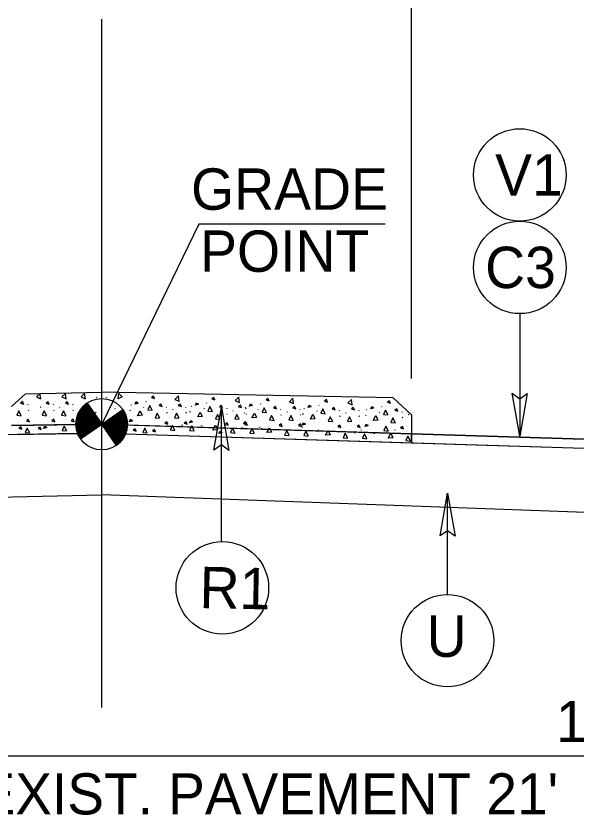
# Model space of a CAD drawing. Extents: x 2176156 to 2177167, y 76401 to 76644.
# Drawn here: x 2176819.12 to 2176834.8, y 76511.75 to 76534.15 of the extents above; entities that cross this region are included whole.
import ezdxf

# ---------------------------------------------------------------- set-up
doc = ezdxf.new("R2010")
doc.units = 0
for name, color, linetype in [('Exist Roads Change in Surface', 7, 'Continuous'), ('Exist Roads Curbs', 7, 'Continuous'), ('Exist Roads Soil', 7, 'Continuous'), ('Exist Structure Minor Culvert Topo', 7, 'Continuous'), ('Old_Level_3', 7, 'Continuous'), ('Prop North Arrow NAD83 for Plan Sheets CELL', 7, 'Continuous'), ('Sheet Plan CELL', 7, 'Continuous')]:
    doc.layers.add(name, color=color, linetype=linetype)

msp = doc.modelspace()

# ---------------------------------------------------------------- linework, layer by layer
at = {"layer": 'Exist Roads Change in Surface'}
for p, q in [((2176821.385, 76523.44), (2176821.375, 76523.464)), ((2176821.652, 76523.44), (2176821.663, 76523.464)), ((2176819.455, 76523.251), (2176819.444, 76523.235)), ((2176820.168, 76523.251), (2176820.157, 76523.235)), ((2176820.707, 76523.251), (2176820.696, 76523.235)), ((2176821.107, 76523.294), (2176821.519, 76522.702)), ((2176822.33, 76523.251), (2176822.341, 76523.235)), ((2176822.764, 76523.336), (2176822.754, 76523.32)), ((2176824.019, 76523.217), (2176824.029, 76523.201)), ((2176824.453, 76523.302), (2176824.442, 76523.286)), ((2176825.968, 76523.272), (2176825.958, 76523.256)), ((2176827.61, 76523.239), (2176827.599, 76523.223)), ((2176819.475, 76523.075), (2176819.464, 76523.099)), ((2176819.809, 76523.183), (2176819.798, 76523.167)), ((2176820.188, 76523.075), (2176820.177, 76523.099)), ((2176820.348, 76523.183), (2176820.337, 76523.167)), ((2176820.727, 76523.075), (2176820.716, 76523.099)), ((2176821.143, 76523.131), (2176821.132, 76523.155)), ((2176821.359, 76523.014), (2176821.348, 76523.038)), ((2176821.519, 76522.702), (2176822.11, 76523.114)), ((2176821.679, 76523.014), (2176821.69, 76523.038)), ((2176821.895, 76523.131), (2176821.905, 76523.155)), ((2176822.31, 76523.075), (2176822.321, 76523.099)), ((2176822.689, 76523.183), (2176822.7, 76523.167)), ((2176823.333, 76523.183), (2176823.322, 76523.167)), ((2176823.353, 76523.007), (2176823.342, 76523.031)), ((2176823.513, 76523.115), (2176823.502, 76523.099)), ((2176823.872, 76523.183), (2176823.861, 76523.167)), ((2176823.892, 76523.007), (2176823.881, 76523.031)), ((2176823.998, 76523.041), (2176824.009, 76523.065)), ((2176824.378, 76523.149), (2176824.388, 76523.133)), ((2176825.021, 76523.149), (2176825.01, 76523.133)), ((2176825.041, 76522.974), (2176825.03, 76522.998)), ((2176825.201, 76523.081), (2176825.191, 76523.065)), ((2176825.514, 76523.011), (2176825.525, 76523.035)), ((2176825.534, 76523.186), (2176825.545, 76523.17)), ((2176825.56, 76523.149), (2176825.55, 76523.133)), ((2176825.58, 76522.974), (2176825.57, 76522.998)), ((2176825.893, 76523.119), (2176825.904, 76523.103)), ((2176826.536, 76523.119), (2176826.526, 76523.103)), ((2176826.717, 76523.051), (2176826.706, 76523.035)), ((2176827.076, 76523.119), (2176827.065, 76523.103)), ((2176827.155, 76522.978), (2176827.166, 76523.002)), ((2176827.176, 76523.154), (2176827.186, 76523.138)), ((2176827.535, 76523.086), (2176827.545, 76523.07)), ((2176828.178, 76523.086), (2176828.167, 76523.07)), ((2176828.358, 76523.018), (2176828.348, 76523.002)), ((2176828.717, 76523.086), (2176828.707, 76523.07)), ((2176828.933, 76523.118), (2176828.944, 76523.102)), ((2176829.292, 76523.051), (2176829.303, 76523.035)), ((2176829.368, 76523.204), (2176829.357, 76523.188)), ((2176829.936, 76523.051), (2176829.925, 76523.035)), ((2176821.026, 76522.843), (2176821.015, 76522.827)), ((2176822.012, 76522.843), (2176822.023, 76522.827)), ((2176826.556, 76522.943), (2176826.546, 76522.967)), ((2176827.096, 76522.943), (2176827.085, 76522.967)), ((2176828.198, 76522.911), (2176828.187, 76522.935)), ((2176828.737, 76522.911), (2176828.727, 76522.935)), ((2176828.913, 76522.943), (2176828.924, 76522.967)), ((2176829.956, 76522.875), (2176829.945, 76522.899)), ((2176830.116, 76522.983), (2176830.106, 76522.967)), ((2176820.926, 76522.292), (2176821.519, 76522.702)), ((2176821.519, 76522.702), (2176820.926, 76522.292)), ((2176821.93, 76522.11), (2176821.519, 76522.702)), ((2176823.779, 76522.659), (2176823.769, 76522.683)), ((2176824.319, 76522.645), (2176824.309, 76522.669)), ((2176825.466, 76522.582), (2176825.456, 76522.606)), ((2176825.94, 76522.607), (2176825.951, 76522.631)), ((2176826.005, 76522.568), (2176825.995, 76522.592)), ((2176827.143, 76522.617), (2176827.132, 76522.601)), ((2176827.58, 76522.532), (2176827.591, 76522.556)), ((2176829.718, 76522.55), (2176829.728, 76522.534)), ((2176826.98, 76522.513), (2176826.97, 76522.537)), ((2176827.52, 76522.499), (2176827.51, 76522.523)), ((2176828.621, 76522.438), (2176828.61, 76522.462)), ((2176828.784, 76522.542), (2176828.773, 76522.526)), ((2176829.16, 76522.424), (2176829.15, 76522.449)), ((2176829.336, 76522.452), (2176829.348, 76522.476))]:
    msp.add_line(p, q, dxfattribs=at)
for points in [[(2176819.809, 76523.412), (2176819.788, 76523.564), (2176819.692, 76523.466), (2176819.806, 76523.413)], [(2176820.522, 76523.412), (2176820.501, 76523.564), (2176820.405, 76523.466), (2176820.519, 76523.413)], [(2176821.061, 76523.412), (2176821.04, 76523.564), (2176820.945, 76523.466), (2176821.059, 76523.413)], [(2176821.976, 76523.412), (2176821.997, 76523.564), (2176822.093, 76523.466), (2176821.979, 76523.413)], [(2176823.001, 76523.422), (2176822.969, 76523.489), (2176822.916, 76523.449), (2176823.001, 76523.422)], [(2176823.687, 76523.345), (2176823.665, 76523.497), (2176823.57, 76523.398), (2176823.684, 76523.345)], [(2176824.689, 76523.388), (2176824.657, 76523.455), (2176824.604, 76523.415), (2176824.689, 76523.388)], [(2176825.375, 76523.311), (2176825.354, 76523.463), (2176825.258, 76523.365), (2176825.372, 76523.312)], [(2176819.333, 76523.269), (2176819.301, 76523.336), (2176819.247, 76523.296), (2176819.333, 76523.269)], [(2176820.045, 76523.269), (2176820.013, 76523.336), (2176819.96, 76523.296), (2176820.045, 76523.269)], [(2176820.585, 76523.269), (2176820.553, 76523.336), (2176820.5, 76523.296), (2176820.585, 76523.269)], [(2176821.158, 76523.22), (2176820.872, 76523.021)], [(2176821.15, 76523.232), (2176820.886, 76523.048)], [(2176821.142, 76523.244), (2176820.902, 76523.077)], [(2176821.133, 76523.256), (2176820.922, 76523.108)], [(2176821.125, 76523.268), (2176820.949, 76523.145)], [(2176821.117, 76523.279), (2176820.983, 76523.186)], [(2176821.109, 76523.291), (2176821.044, 76523.246)], [(2176822.453, 76523.269), (2176822.485, 76523.336), (2176822.538, 76523.296), (2176822.453, 76523.269)], [(2176822.935, 76523.095), (2176822.863, 76523.23), (2176822.807, 76523.105), (2176822.932, 76523.095)], [(2176823.21, 76523.202), (2176823.178, 76523.268), (2176823.125, 76523.228), (2176823.21, 76523.202)], [(2176823.75, 76523.202), (2176823.718, 76523.268), (2176823.664, 76523.228), (2176823.75, 76523.202)], [(2176824.141, 76523.235), (2176824.173, 76523.302), (2176824.226, 76523.262), (2176824.141, 76523.235)], [(2176824.899, 76523.168), (2176824.867, 76523.234), (2176824.813, 76523.194), (2176824.899, 76523.168)], [(2176825.438, 76523.168), (2176825.406, 76523.234), (2176825.353, 76523.194), (2176825.438, 76523.168)], [(2176825.656, 76523.205), (2176825.688, 76523.272), (2176825.742, 76523.232), (2176825.656, 76523.205)], [(2176826.205, 76523.358), (2176826.173, 76523.424), (2176826.12, 76523.385), (2176826.205, 76523.358)], [(2176826.89, 76523.28), (2176826.869, 76523.433), (2176826.774, 76523.334), (2176826.888, 76523.281)], [(2176827.298, 76523.172), (2176827.33, 76523.239), (2176827.383, 76523.199), (2176827.298, 76523.172)], [(2176827.846, 76523.325), (2176827.814, 76523.392), (2176827.761, 76523.352), (2176827.846, 76523.325)], [(2176828.532, 76523.248), (2176828.511, 76523.4), (2176828.415, 76523.301), (2176828.529, 76523.249)], [(2176829.604, 76523.29), (2176829.572, 76523.357), (2176829.519, 76523.317), (2176829.604, 76523.29)], [(2176819.266, 76522.942), (2176819.194, 76523.078), (2176819.138, 76522.952), (2176819.263, 76522.942)], [(2176819.979, 76522.942), (2176819.907, 76523.078), (2176819.851, 76522.952), (2176819.976, 76522.942)], [(2176820.518, 76522.942), (2176820.446, 76523.078), (2176820.39, 76522.952), (2176820.516, 76522.942)], [(2176821.274, 76523.054), (2176820.798, 76522.723)], [(2176821.282, 76523.043), (2176820.798, 76522.706)], [(2176821.29, 76523.031), (2176820.798, 76522.689)], [(2176821.265, 76523.066), (2176820.799, 76522.742)], [(2176821.298, 76523.019), (2176820.799, 76522.671)], [(2176821.306, 76523.007), (2176820.799, 76522.654)], [(2176821.257, 76523.078), (2176820.8, 76522.76)], [(2176821.315, 76522.995), (2176820.801, 76522.638)], [(2176821.249, 76523.09), (2176820.802, 76522.779)], [(2176821.241, 76523.102), (2176820.804, 76522.798)], [(2176821.232, 76523.114), (2176820.806, 76522.817)], [(2176821.224, 76523.126), (2176820.81, 76522.837)], [(2176821.216, 76523.137), (2176820.815, 76522.858)], [(2176821.208, 76523.149), (2176820.82, 76522.879)], [(2176821.199, 76523.161), (2176820.826, 76522.901)], [(2176821.191, 76523.173), (2176820.832, 76522.923)], [(2176821.183, 76523.185), (2176820.84, 76522.946)], [(2176821.175, 76523.196), (2176820.849, 76522.97)], [(2176821.166, 76523.208), (2176820.859, 76522.994)], [(2176822.114, 76523.109), (2176822.114, 76523.109), (2176821.522, 76522.697)], [(2176822.122, 76523.097), (2176821.531, 76522.685)], [(2176822.129, 76523.084), (2176821.539, 76522.673)], [(2176822.137, 76523.072), (2176821.547, 76522.661)], [(2176822.144, 76523.059), (2176821.555, 76522.65)], [(2176822.151, 76523.047), (2176821.564, 76522.638)], [(2176822.158, 76523.034), (2176821.572, 76522.626)], [(2176822.165, 76523.021), (2176821.58, 76522.614)], [(2176822.172, 76523.008), (2176821.588, 76522.602)], [(2176822.178, 76522.995), (2176821.596, 76522.59)], [(2176822.519, 76522.942), (2176822.591, 76523.078), (2176822.647, 76522.952), (2176822.522, 76522.942)], [(2176823.144, 76522.874), (2176823.072, 76523.01), (2176823.016, 76522.885), (2176823.141, 76522.874)], [(2176823.683, 76522.874), (2176823.611, 76523.01), (2176823.555, 76522.885), (2176823.68, 76522.874)], [(2176824.207, 76522.908), (2176824.279, 76523.044), (2176824.335, 76522.919), (2176824.21, 76522.908)], [(2176824.623, 76523.061), (2176824.551, 76523.197), (2176824.495, 76523.072), (2176824.62, 76523.061)], [(2176825.723, 76522.878), (2176825.795, 76523.014), (2176825.851, 76522.888), (2176825.726, 76522.878)], [(2176826.138, 76523.031), (2176826.066, 76523.166), (2176826.01, 76523.041), (2176826.136, 76523.031)], [(2176826.414, 76523.138), (2176826.382, 76523.204), (2176826.329, 76523.164), (2176826.414, 76523.138)], [(2176826.953, 76523.138), (2176826.921, 76523.204), (2176826.868, 76523.164), (2176826.953, 76523.138)], [(2176827.78, 76522.998), (2176827.708, 76523.134), (2176827.652, 76523.008), (2176827.777, 76522.998)], [(2176828.056, 76523.105), (2176828.024, 76523.171), (2176827.97, 76523.131), (2176828.056, 76523.105)], [(2176828.595, 76523.105), (2176828.563, 76523.171), (2176828.51, 76523.131), (2176828.595, 76523.105)], [(2176829.056, 76523.137), (2176829.088, 76523.204), (2176829.141, 76523.164), (2176829.056, 76523.137)], [(2176829.538, 76522.963), (2176829.466, 76523.098), (2176829.41, 76522.973), (2176829.535, 76522.963)], [(2176829.813, 76523.07), (2176829.781, 76523.136), (2176829.728, 76523.096), (2176829.813, 76523.07)], [(2176819.494, 76522.774), (2176819.462, 76522.841), (2176819.408, 76522.801), (2176819.494, 76522.774)], [(2176820.206, 76522.774), (2176820.174, 76522.841), (2176820.121, 76522.801), (2176820.206, 76522.774)], [(2176820.746, 76522.774), (2176820.714, 76522.841), (2176820.661, 76522.801), (2176820.746, 76522.774)], [(2176821.323, 76522.983), (2176820.802, 76522.621)], [(2176821.331, 76522.972), (2176820.804, 76522.605)], [(2176821.339, 76522.96), (2176820.807, 76522.589)], [(2176821.348, 76522.948), (2176820.81, 76522.574)], [(2176821.356, 76522.936), (2176820.813, 76522.558)], [(2176821.364, 76522.924), (2176820.816, 76522.543)], [(2176821.372, 76522.913), (2176820.819, 76522.527)], [(2176821.381, 76522.901), (2176820.823, 76522.513)], [(2176821.389, 76522.889), (2176820.827, 76522.498)], [(2176821.397, 76522.877), (2176820.832, 76522.484)], [(2176821.405, 76522.865), (2176820.837, 76522.47)], [(2176821.413, 76522.853), (2176820.842, 76522.455)], [(2176821.422, 76522.841), (2176820.847, 76522.442)], [(2176821.43, 76522.83), (2176820.853, 76522.428)], [(2176821.438, 76522.818), (2176820.858, 76522.414)], [(2176821.446, 76522.806), (2176820.864, 76522.401)], [(2176821.455, 76522.794), (2176820.871, 76522.388)], [(2176821.463, 76522.782), (2176820.877, 76522.374)], [(2176821.471, 76522.771), (2176820.883, 76522.362)], [(2176822.183, 76522.981), (2176821.605, 76522.579)], [(2176822.189, 76522.967), (2176821.613, 76522.567)], [(2176822.194, 76522.954), (2176821.621, 76522.555)], [(2176822.199, 76522.939), (2176821.629, 76522.543)], [(2176822.204, 76522.926), (2176821.638, 76522.531)], [(2176822.209, 76522.911), (2176821.646, 76522.519)], [(2176822.213, 76522.896), (2176821.654, 76522.508)], [(2176822.217, 76522.882), (2176821.662, 76522.496)], [(2176822.22, 76522.866), (2176821.671, 76522.484)], [(2176822.223, 76522.851), (2176821.679, 76522.472)], [(2176822.226, 76522.835), (2176821.687, 76522.46)], [(2176822.229, 76522.82), (2176821.695, 76522.448)], [(2176822.232, 76522.804), (2176821.704, 76522.437)], [(2176822.234, 76522.788), (2176821.712, 76522.425)], [(2176822.235, 76522.772), (2176821.72, 76522.413)], [(2176822.292, 76522.774), (2176822.324, 76522.841), (2176822.377, 76522.801), (2176822.292, 76522.774)], [(2176823.371, 76522.706), (2176823.339, 76522.773), (2176823.286, 76522.733), (2176823.371, 76522.706)], [(2176823.911, 76522.706), (2176823.879, 76522.773), (2176823.826, 76522.733), (2176823.911, 76522.706)], [(2176823.98, 76522.74), (2176824.012, 76522.807), (2176824.065, 76522.767), (2176823.98, 76522.74)], [(2176824.832, 76522.841), (2176824.76, 76522.976), (2176824.704, 76522.851), (2176824.829, 76522.841)], [(2176825.371, 76522.841), (2176825.299, 76522.976), (2176825.244, 76522.851), (2176825.369, 76522.841)], [(2176825.495, 76522.71), (2176825.527, 76522.776), (2176825.581, 76522.736), (2176825.495, 76522.71)], [(2176826.347, 76522.81), (2176826.275, 76522.946), (2176826.22, 76522.821), (2176826.345, 76522.81)], [(2176826.887, 76522.81), (2176826.815, 76522.946), (2176826.759, 76522.821), (2176826.884, 76522.81)], [(2176827.364, 76522.845), (2176827.436, 76522.981), (2176827.492, 76522.856), (2176827.367, 76522.845)], [(2176827.989, 76522.777), (2176827.917, 76522.913), (2176827.861, 76522.788), (2176827.986, 76522.777)], [(2176828.528, 76522.777), (2176828.456, 76522.913), (2176828.401, 76522.788), (2176828.526, 76522.777)], [(2176829.122, 76522.81), (2176829.194, 76522.946), (2176829.25, 76522.82), (2176829.125, 76522.81)], [(2176829.747, 76522.742), (2176829.675, 76522.878), (2176829.619, 76522.753), (2176829.744, 76522.742)], [(2176819.283, 76522.563), (2176819.252, 76522.631), (2176819.198, 76522.592), (2176819.283, 76522.563)], [(2176819.501, 76522.46), (2176819.429, 76522.596), (2176819.373, 76522.471), (2176819.499, 76522.46)], [(2176819.822, 76522.55), (2176819.792, 76522.617), (2176819.737, 76522.578), (2176819.822, 76522.55)], [(2176819.892, 76522.582), (2176819.925, 76522.647), (2176819.978, 76522.606), (2176819.892, 76522.582)], [(2176820.537, 76522.517), (2176820.465, 76522.652), (2176820.409, 76522.527), (2176820.535, 76522.517)], [(2176821.479, 76522.759), (2176820.89, 76522.349)], [(2176821.488, 76522.747), (2176820.897, 76522.336)], [(2176821.496, 76522.735), (2176820.905, 76522.324)], [(2176821.504, 76522.723), (2176820.912, 76522.311)], [(2176821.512, 76522.711), (2176820.921, 76522.3), (2176820.921, 76522.3)], [(2176822.237, 76522.755), (2176821.728, 76522.401)], [(2176822.239, 76522.739), (2176821.736, 76522.389)], [(2176822.239, 76522.721), (2176821.745, 76522.377)], [(2176822.239, 76522.704), (2176821.753, 76522.366)], [(2176822.239, 76522.686), (2176821.761, 76522.354)], [(2176822.239, 76522.669), (2176821.769, 76522.342)], [(2176822.238, 76522.65), (2176821.778, 76522.33)], [(2176822.236, 76522.631), (2176821.786, 76522.318)], [(2176822.233, 76522.612), (2176821.794, 76522.306)], [(2176822.231, 76522.593), (2176821.802, 76522.295)], [(2176822.227, 76522.573), (2176821.811, 76522.283)], [(2176822.224, 76522.553), (2176821.819, 76522.271)], [(2176822.484, 76522.504), (2176822.453, 76522.572), (2176822.399, 76522.533), (2176822.484, 76522.504)], [(2176822.794, 76522.46), (2176822.722, 76522.596), (2176822.666, 76522.471), (2176822.791, 76522.46)], [(2176823.023, 76522.491), (2176822.993, 76522.558), (2176822.938, 76522.519), (2176823.023, 76522.491)], [(2176823.567, 76522.531), (2176823.499, 76522.669), (2176823.439, 76522.545), (2176823.564, 76522.531)], [(2176824.106, 76522.517), (2176824.038, 76522.655), (2176823.979, 76522.531), (2176824.104, 76522.517)], [(2176824.631, 76522.538), (2176824.707, 76522.672), (2176824.759, 76522.545), (2176824.634, 76522.538)], [(2176825.06, 76522.673), (2176825.028, 76522.739), (2176824.974, 76522.699), (2176825.06, 76522.673)], [(2176825.254, 76522.454), (2176825.185, 76522.592), (2176825.126, 76522.468), (2176825.251, 76522.454)], [(2176825.599, 76522.673), (2176825.567, 76522.739), (2176825.514, 76522.699), (2176825.599, 76522.673)], [(2176825.793, 76522.44), (2176825.725, 76522.578), (2176825.666, 76522.454), (2176825.79, 76522.44)], [(2176826.145, 76522.469), (2176826.221, 76522.603), (2176826.274, 76522.476), (2176826.148, 76522.468)], [(2176826.575, 76522.642), (2176826.543, 76522.709), (2176826.49, 76522.669), (2176826.575, 76522.642)], [(2176827.114, 76522.642), (2176827.083, 76522.709), (2176827.029, 76522.669), (2176827.114, 76522.642)], [(2176827.137, 76522.677), (2176827.169, 76522.744), (2176827.222, 76522.704), (2176827.137, 76522.677)], [(2176828.217, 76522.61), (2176828.185, 76522.676), (2176828.131, 76522.636), (2176828.217, 76522.61)], [(2176828.756, 76522.61), (2176828.724, 76522.676), (2176828.671, 76522.636), (2176828.756, 76522.61)], [(2176828.895, 76522.642), (2176828.927, 76522.708), (2176828.98, 76522.668), (2176828.895, 76522.642)], [(2176829.548, 76522.512), (2176829.476, 76522.648), (2176829.421, 76522.522), (2176829.546, 76522.512)], [(2176829.974, 76522.574), (2176829.942, 76522.641), (2176829.889, 76522.601), (2176829.974, 76522.574)], [(2176822.219, 76522.532), (2176821.827, 76522.259)], [(2176822.213, 76522.51), (2176821.835, 76522.247)], [(2176822.206, 76522.488), (2176821.844, 76522.235)], [(2176822.199, 76522.465), (2176821.852, 76522.224)], [(2176822.19, 76522.441), (2176821.86, 76522.212)], [(2176822.18, 76522.417), (2176821.868, 76522.2)], [(2176822.168, 76522.391), (2176821.876, 76522.188)], [(2176822.156, 76522.365), (2176821.885, 76522.176)], [(2176822.139, 76522.335), (2176821.893, 76522.164)], [(2176824.802, 76522.445), (2176824.836, 76522.51), (2176824.888, 76522.469), (2176824.802, 76522.445)], [(2176826.768, 76522.385), (2176826.7, 76522.523), (2176826.64, 76522.399), (2176826.765, 76522.385)], [(2176827.307, 76522.371), (2176827.239, 76522.509), (2176827.18, 76522.385), (2176827.305, 76522.371)], [(2176827.786, 76522.394), (2176827.861, 76522.528), (2176827.914, 76522.401), (2176827.788, 76522.394)], [(2176828.408, 76522.31), (2176828.34, 76522.448), (2176828.281, 76522.324), (2176828.406, 76522.31)], [(2176828.947, 76522.297), (2176828.879, 76522.434), (2176828.82, 76522.31), (2176828.945, 76522.297)], [(2176829.542, 76522.314), (2176829.617, 76522.448), (2176829.67, 76522.321), (2176829.545, 76522.314)], [(2176830.165, 76522.23), (2176830.096, 76522.368), (2176830.037, 76522.244), (2176830.162, 76522.23)], [(2176822.119, 76522.304), (2176821.901, 76522.153)], [(2176822.095, 76522.27), (2176821.909, 76522.141)], [(2176822.062, 76522.23), (2176821.918, 76522.129)], [(2176822.01, 76522.176), (2176821.926, 76522.117)]]:
    msp.add_lwpolyline(points, dxfattribs=at)
msp.add_circle((2176821.518, 76522.703), 0.721, dxfattribs=at)
for start, end in [(124.8249, 214.8249), (304.8249, 34.8249)]:
    msp.add_arc((2176821.518, 76522.703), 0.721, start, end, dxfattribs=at)
at = {"layer": 'Exist Roads Curbs'}
for p, q in [((2176818.989, 76522.665), (2176821.519, 76522.702)), ((2176820.798, 76522.691), (2176818.989, 76522.665)), ((2176820.799, 76522.654), (2176820.799, 76522.654)), ((2176820.804, 76522.605), (2176820.804, 76522.605)), ((2176821.519, 76522.702), (2176830.194, 76522.432)), ((2176822.224, 76522.553), (2176822.223, 76522.552)), ((2176822.227, 76522.573), (2176822.227, 76522.573)), ((2176822.231, 76522.593), (2176822.231, 76522.593)), ((2176822.238, 76522.65), (2176822.237, 76522.65)), ((2176822.239, 76522.669), (2176822.238, 76522.668)), ((2176830.194, 76522.432), (2176822.239, 76522.68)), ((2176820.846, 76522.442), (2176806.733, 76522.232)), ((2176818.989, 76522.415), (2176820.846, 76522.442)), ((2176820.819, 76522.527), (2176820.819, 76522.528)), ((2176820.823, 76522.513), (2176820.823, 76522.513)), ((2176820.832, 76522.484), (2176820.832, 76522.484)), ((2176822.186, 76522.431), (2176842.453, 76521.799)), ((2176822.186, 76522.431), (2176830.194, 76522.182)), ((2176822.199, 76522.465), (2176822.199, 76522.465)), ((2176822.206, 76522.488), (2176822.206, 76522.488)), ((2176822.219, 76522.532), (2176822.219, 76522.531)), ((2176830.194, 76522.432), (2176842.194, 76522.057)), ((2176842.194, 76522.057), (2176830.194, 76522.432)), ((2176830.194, 76522.432), (2176830.194, 76522.182)), ((2176830.194, 76522.182), (2176830.194, 76522.432)), ((2176830.194, 76522.182), (2176838.376, 76521.926))]:
    msp.add_line(p, q, dxfattribs=at)
for points in [[(2176820.799, 76522.654), (2176820.799, 76522.654)], [(2176820.804, 76522.605), (2176820.804, 76522.605)], [(2176822.223, 76522.553), (2176822.224, 76522.553)], [(2176822.227, 76522.573), (2176822.227, 76522.573)], [(2176822.231, 76522.593), (2176822.231, 76522.593)], [(2176822.237, 76522.65), (2176822.238, 76522.65)], [(2176822.238, 76522.669), (2176822.239, 76522.669)], [(2176820.819, 76522.527), (2176820.819, 76522.527)], [(2176820.823, 76522.513), (2176820.823, 76522.513)], [(2176820.832, 76522.484), (2176820.832, 76522.484)], [(2176822.199, 76522.465), (2176822.199, 76522.465)], [(2176822.206, 76522.488), (2176822.206, 76522.488)], [(2176822.219, 76522.532), (2176822.219, 76522.532)], [(2176830.194, 76522.182), (2176830.194, 76522.182)]]:
    msp.add_lwpolyline(points, dxfattribs=at)
for start, end in [(180.9136, 182.5146), (182.5146, 183.8761), (183.8895, 187.8094), (187.8245, 190.3336), (190.3336, 191.5882), (191.5882, 194.0754), (346.2648, 347.9455), (347.9775, 349.598), (349.5984, 351.2038), (351.2196, 352.7539), (352.7539, 355.7778), (355.8127, 357.2394), (357.2652, 358.1523), (194.0907, 195.2968), (195.2976, 197.7127), (197.7154, 201.2126), (337.8613, 340.731), (340.7368, 342.6429), (342.646, 346.2404)]:
    msp.add_arc((2176821.518, 76522.703), 0.721, start, end, dxfattribs=at)
at = {"layer": 'Exist Roads Soil'}
for p, q in [((2176818.989, 76523.196), (2176819.383, 76523.559)), ((2176819.383, 76523.559), (2176821.519, 76523.602)), ((2176829.677, 76523.439), (2176821.519, 76523.602)), ((2176830.194, 76522.963), (2176829.677, 76523.439)), ((2176830.194, 76522.963), (2176830.194, 76522.182))]:
    msp.add_line(p, q, dxfattribs=at)
at = {"layer": 'Old_Level_3'}
for p, q in [((2176830.194, 76524.058), (2176830.194, 76536.723)), ((2176830.194, 76523.982), (2176830.194, 76536.68)), ((2176821.519, 76514.763), (2176821.519, 76534.056)), ((2176812.066, 76513.403), (2176838.376, 76513.403))]:
    msp.add_line(p, q, dxfattribs=at)
at = {"layer": 'Prop North Arrow NAD83 for Plan Sheets CELL'}
for p, q in [((2176824.242, 76528.31), (2176821.519, 76522.702)), ((2176829.461, 76528.31), (2176824.242, 76528.31)), ((2176833.23, 76525.803), (2176833.23, 76522.363)), ((2176824.87, 76519.411), (2176824.87, 76523.176)), ((2176831.204, 76517.93), (2176831.204, 76520.772))]:
    msp.add_line(p, q, dxfattribs=at)
for points in [[(2176833.437, 76523.563), (2176833.23, 76522.363), (2176833.017, 76523.569), (2176833.23, 76523.416)], [(2176824.663, 76521.976), (2176824.87, 76523.176), (2176825.083, 76521.97), (2176824.87, 76522.123)], [(2176830.997, 76519.572), (2176831.204, 76520.772), (2176831.417, 76519.565), (2176831.204, 76519.718)]]:
    msp.add_lwpolyline(points, close=True, dxfattribs=at)
for centre in [(2176833.23, 76529.691), (2176833.23, 76527.099), (2176824.897, 76518.116), (2176831.204, 76516.634)]:
    msp.add_circle(centre, 1.296, dxfattribs=at)
at = {"layer": 'Sheet Plan CELL'}
for p in [(2176812.069, 76520.526), (2176838.376, 76520.111)]:
    msp.add_line(p, (2176821.519, 76520.722), dxfattribs=at)

# ---------------------------------------------------------------- texts
at = {"layer": 'Exist Structure Minor Culvert Topo'}
msp.add_text("EXIST. PAVEMENT 21'", height=1.15334, dxfattribs=at).set_placement((2176818.066, 76511.762))
at = {"layer": 'Prop North Arrow NAD83 for Plan Sheets CELL'}
for s, rotation, p in [('V1', 0.0003, (2176832.537, 76529.111)), ('GRADE', 0.0002, (2176824.02, 76528.715)), ('POINT', 0.0002, (2176824.273, 76526.975)), ('C3', 0.0003, (2176832.257, 76526.519)), ('R1', 358.8249, (2176824.249, 76517.549)), ('U', 0.0003, (2176830.618, 76516.18))]:
    msp.add_text(s, height=1.16, rotation=rotation, dxfattribs=at).set_placement(p)
msp.add_text('11"', height=1.1533, dxfattribs=at).set_placement((2176834.242, 76513.794))

doc.saveas('drawing.dxf')
